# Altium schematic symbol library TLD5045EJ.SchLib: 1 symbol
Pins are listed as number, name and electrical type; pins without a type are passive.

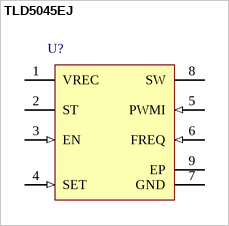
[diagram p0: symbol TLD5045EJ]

## TLD5045EJ
designator U?
700 mA High Integration - DC/DC Step-Down Converter, 5 to 40 V, -40 to 150 degC, PG-DSO-8-27, Reel, Pb-free; Manufacturer: Infineon; PartNumber: TLD5045EJ; Green: TRUE; Topology: DC-DC Buck; VS (max): 40 V; VS (min): 5 V
footprint INF-PG-DSO-8-27_N (SOP, 8-Leads, Body 4.9x3.9mm, Pitch 1.27mm, Thermal Pad 3.2x2.85mm, IPC Medium Density)
footprint INF-PG-DSO-8-27_L (SOP, 8-Leads, Body 4.9x3.9mm, Pitch 1.27mm, Thermal Pad 3.2x2.85mm, IPC High Density)
footprint INF-PG-DSO-8-27_M (SOP, 8-Leads, Body 4.9x3.9mm, Pitch 1.27mm, Thermal Pad 3.2x2.85mm, IPC Low Density)
pins: 1 VREC (power) "Voltage Recirculation Output and Internal Supply Input; This pin is the supply pin of the IC (see block diagram). Furthermore the cathode of the integrated fast freewheeling diode is connected to this pin as well.", 2 ST (oc) "Status Output;Open collector diagnostic output to indicate an open load failure. Refer to Chapter 7 for more details.", 3 EN (in) "Enable; Apply logic HIGH signal to enable the device", 4 SET (in) "SET Input;Connect a low power resistor to adjust the output current.", 5 PWMI (in) "PWM Input; PWM signal for dimming LEDs. Connect external R and C combination to achieve an auto PWM-dimming function with defined frequency and duty cycle. 1) internal PWM dimming function (external RC connected to GND) 2) (See Datasheet)", 6 FREQ (in) "FREQuency Select Input; Connect external Resistor and Capacitor to GND to set the OFF-time of the switching frequency.", 7 GND (power) "Ground; Connect to system ground.", 8 SW (oc) "Integrated Power-Switch Output; Collector of the integrated NPN-power transistor.", 9 EP (power) "Exposed Pad; Connect to external heatspreading copper area with electrically GND (e.g. inner GND layer of the PCB via thermal vias)"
